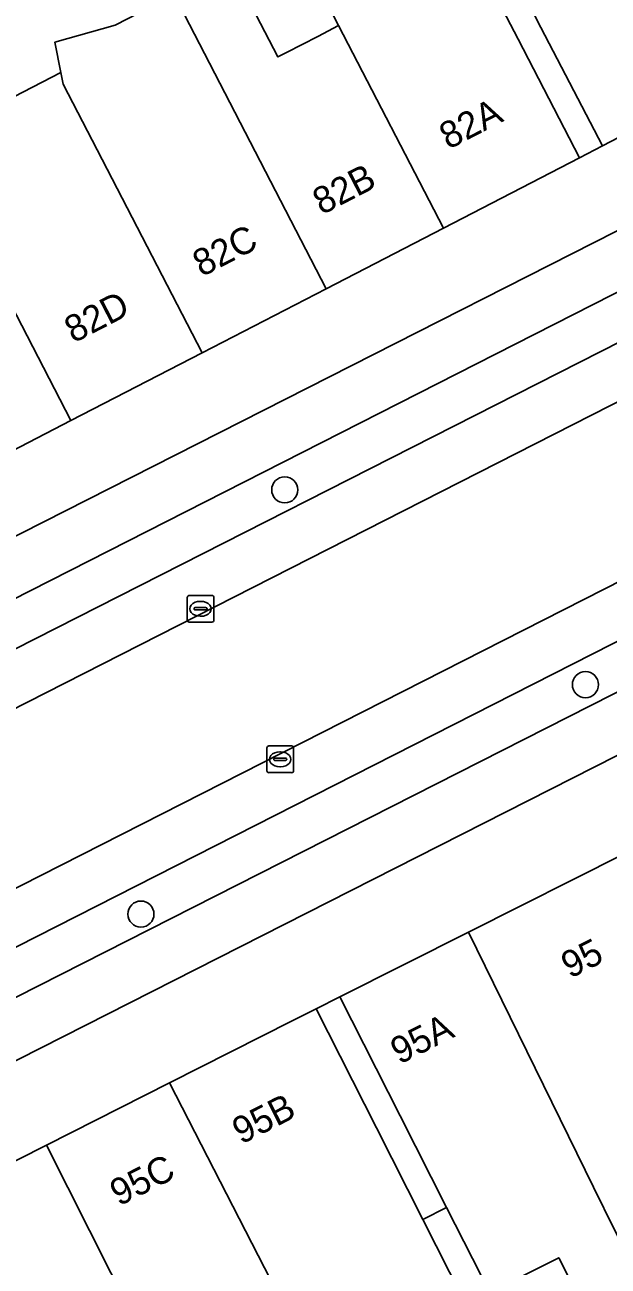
# Model space of a CAD drawing. Extents: x 158086 to 159499, y 382904 to 383981.
# Drawn here: x 158897.48 to 158919.33, y 383189.15 to 383235.68 of the extents above; entities that cross this region are included whole.
import ezdxf

# ---------------------------------------------------------------- set-up
doc = ezdxf.new("R2010")
doc.units = 0
for name, color, linetype in [('IMGEO_Berm_open', 7, 'Continuous'), ('IMGEO_Boom', 7, 'Continuous'), ('IMGEO_Erf', 7, 'Continuous'), ('IMGEO_Fietspad_gesloten', 7, 'Continuous'), ('IMGEO_Kolk', 7, 'Continuous'), ('IMGEO_Pand', 7, 'Continuous'), ('IMGEO_Pand_nummerreeks', 7, 'Continuous'), ('IMGEO_Pand_overbouw', 7, 'Continuous'), ('IMGEO_Parkeervlak_open', 7, 'Continuous'), ('IMGEO_Rijbaan_lokaal_gesloten', 7, 'Continuous'), ('IMGEO_Voetpad_open', 7, 'Continuous')]:
    doc.layers.add(name, color=color, linetype=linetype)

msp = doc.modelspace()

# ---------------------------------------------------------------- linework, layer by layer
at = {"layer": 'IMGEO_Berm_open'}
for points in [[(158877.802, 383202.135), (158878.263, 383202.712), (158937.072, 383232.587), (158946.787, 383237.376)], [(158941.643, 383236.699), (158932.546, 383232.204), (158896.237, 383213.737), (158887.748, 383209.162), (158884.368, 383207.233)], [(158934.379, 383218.139), (158933.615, 383219.659), (158877.108, 383190.925)], [(158874.019, 383187.49), (158934.379, 383218.139)]]:
    msp.add_lwpolyline(points, dxfattribs=at)
at = {"layer": 'IMGEO_Boom'}
for centre in [(158907.213, 383218.248), (158918.478, 383210.947), (158901.826, 383202.348)]:
    msp.add_circle(centre, 0.489, dxfattribs=at)
at = {"layer": 'IMGEO_Erf'}
for points in [[(158905.187, 383237.9), (158906.958, 383234.473), (158907.274, 383234.636), (158908.45, 383235.244), (158909.232, 383235.648), (158907.489, 383239.022)], [(158895.996, 383232.429), (158898.83, 383233.894), (158898.601, 383235.024), (158900.858, 383235.663), (158903.073, 383236.808)], [(158918.653, 383187.148), (158917.481, 383189.469), (158917.287, 383189.371), (158914.893, 383188.161), (158913.276, 383191.353), (158911.536, 383194.79), (158909.279, 383199.249), (158908.386, 383198.799), (158910.645, 383194.339), (158912.385, 383190.902), (158913.884, 383187.942)]]:
    msp.add_lwpolyline(points, dxfattribs=at)
at = {"layer": 'IMGEO_Fietspad_gesloten'}
for points in [[(158952.602, 383244.197), (158936.1, 383236.306), (158892.392, 383214.111), (158880.945, 383207.777), (158877.306, 383206.045)], [(158884.368, 383207.233), (158887.748, 383209.162), (158896.237, 383213.737), (158932.546, 383232.204), (158941.643, 383236.699)], [(158955.767, 383229.049), (158938.183, 383220.111), (158934.379, 383218.139), (158874.019, 383187.49), (158869.478, 383185.143), (158867.264, 383184.027), (158868.202, 383182.167), (158958.642, 383228.082)]]:
    msp.add_lwpolyline(points, dxfattribs=at)
at = {"layer": 'IMGEO_Kolk'}
for p, q in [((158903.56, 383213.364), (158903.56, 383214.216)), ((158903.635, 383214.29), (158904.487, 383214.29)), ((158904.048, 383214.07), (158904.073, 383214.07)), ((158904.561, 383214.216), (158904.561, 383213.364)), ((158903.819, 383213.784), (158903.819, 383213.796)), ((158904.257, 383213.747), (158903.859, 383213.747)), ((158903.862, 383213.833), (158904.26, 383213.833)), ((158904.303, 383213.796), (158904.303, 383213.784)), ((158904.487, 383213.29), (158903.635, 383213.29)), ((158904.071, 383213.51), (158904.046, 383213.51)), ((158906.545, 383207.723), (158906.545, 383208.575)), ((158906.62, 383208.649), (158907.472, 383208.649)), ((158907.033, 383208.429), (158907.058, 383208.429)), ((158907.546, 383208.575), (158907.546, 383207.723)), ((158906.804, 383208.143), (158906.804, 383208.155)), ((158907.242, 383208.106), (158906.844, 383208.106)), ((158906.847, 383208.192), (158907.245, 383208.192)), ((158907.288, 383208.155), (158907.288, 383208.143)), ((158907.472, 383207.649), (158906.62, 383207.649)), ((158907.056, 383207.869), (158907.031, 383207.869))]:
    msp.add_line(p, q, dxfattribs=at)
for points in [[(158903.56, 383213.364), (158903.56, 383214.216)], [(158903.635, 383214.29), (158904.487, 383214.29)], [(158904.561, 383214.216), (158904.561, 383213.364)], [(158904.487, 383213.29), (158903.635, 383213.29)], [(158906.545, 383207.723), (158906.545, 383208.575)], [(158906.62, 383208.649), (158907.472, 383208.649)], [(158907.546, 383208.575), (158907.546, 383207.723)], [(158907.472, 383207.649), (158906.62, 383207.649)]]:
    msp.add_lwpolyline(points, dxfattribs=at)
for centre, radius, start, end in [((158903.637, 383214.214), 0.0765, 91.552, 178.448), ((158903.637, 383214.214), 0.0765, 91.552, 178.448), ((158904.485, 383214.214), 0.0765, 1.552, 88.448), ((158904.485, 383214.214), 0.0765, 1.552, 88.448), ((158903.859, 383213.793), 0.0403, 85.8775, 175.7526), ((158903.856, 383213.783), 0.0366, 178.938, 274.7102), ((158904.26, 383213.79), 0.043, 264.8664, 352.4533), ((158904.264, 383213.795), 0.0386, 1.7309, 96.639), ((158903.637, 383213.366), 0.0765, 181.552, 268.448), ((158903.637, 383213.366), 0.0765, 181.552, 268.448), ((158904.485, 383213.366), 0.0765, 271.552, 358.448), ((158904.485, 383213.366), 0.0765, 271.552, 358.448), ((158906.622, 383208.573), 0.0765, 91.552, 178.448), ((158906.622, 383208.573), 0.0765, 91.552, 178.448), ((158907.47, 383208.573), 0.0765, 1.552, 88.448), ((158907.47, 383208.573), 0.0765, 1.552, 88.448), ((158906.844, 383208.152), 0.0403, 85.8775, 175.7526), ((158906.841, 383208.142), 0.0366, 178.938, 274.7102), ((158907.245, 383208.149), 0.043, 264.8664, 352.4533), ((158907.249, 383208.154), 0.0386, 1.7309, 96.639), ((158906.622, 383207.725), 0.0765, 181.552, 268.448), ((158906.622, 383207.725), 0.0765, 181.552, 268.448), ((158907.47, 383207.725), 0.0765, 271.552, 358.448), ((158907.47, 383207.725), 0.0765, 271.552, 358.448)]:
    msp.add_arc(centre, radius, start, end, dxfattribs=at)
for centre, major_axis, ratio, start_param, end_param in [((158904.047, 383213.79), (-0.387, 0.002), 0.722429, 4.712389, 7.853982), ((158904.072, 383213.79), (-0.39, 0.002), 0.717154, 1.570796, 4.712389), ((158907.032, 383208.149), (-0.387, 0.002), 0.722429, 4.712389, 7.853982), ((158907.057, 383208.149), (-0.39, 0.002), 0.717154, 1.570796, 4.712389)]:
    msp.add_ellipse(centre, major_axis=major_axis, ratio=ratio, start_param=start_param, end_param=end_param, dxfattribs=at)
at = {"layer": 'IMGEO_Pand'}
for points in [[(158918.51, 383245.411), (158915.333, 383244.713), (158916.684, 383242.097), (158917.505, 383240.514), (158914.974, 383239.199), (158916.813, 383235.583), (158919.116, 383231.144), (158924.425, 383233.898), (158923.549, 383235.588)], [(158915.964, 383235.134), (158914.35, 383238.239), (158911.655, 383236.87), (158909.86, 383240.343), (158907.489, 383239.022), (158909.232, 383235.648), (158913.156, 383228.054), (158918.259, 383230.691)], [(158909.232, 383235.648), (158908.45, 383235.244), (158907.274, 383234.636), (158906.958, 383234.473), (158905.187, 383237.9), (158903.073, 383236.808), (158908.768, 383225.787), (158913.156, 383228.054)], [(158903.073, 383236.808), (158900.858, 383235.663), (158898.601, 383235.024), (158898.83, 383233.894), (158898.919, 383233.453), (158900.192, 383230.993), (158904.122, 383223.386), (158908.768, 383225.787)], [(158900.192, 383230.993), (158898.919, 383233.453), (158898.83, 383233.894), (158895.996, 383232.429), (158895.677, 383233.046), (158893.486, 383231.914), (158899.205, 383220.845), (158904.122, 383223.386)], [(158893.486, 383231.914), (158890.868, 383230.561), (158888.104, 383229.133), (158889.842, 383225.744), (158891.508, 383222.496), (158893.803, 383218.054), (158899.205, 383220.845)], [(158922.21, 383200.164), (158919.952, 383204.624), (158914.098, 383201.676), (158918.782, 383192.11), (158919.561, 383190.519), (158920.112, 383189.428), (158925.743, 383192.27), (158924.003, 383195.718), (158924.368, 383195.902), (158924.072, 383196.486)], [(158914.098, 383201.676), (158909.279, 383199.249), (158911.536, 383194.79), (158913.276, 383191.353), (158914.893, 383188.161), (158917.287, 383189.371), (158917.481, 383189.469), (158918.653, 383187.148), (158920.733, 383188.198), (158920.112, 383189.428), (158919.561, 383190.519), (158918.782, 383192.11)], [(158910.645, 383194.339), (158908.386, 383198.799), (158907.494, 383198.348), (158902.902, 383196.023), (158906.935, 383188.166), (158907.105, 383188.252), (158908.744, 383185.007), (158911.48, 383186.389), (158911.344, 383186.659), (158913.884, 383187.942), (158912.385, 383190.902)], [(158898.286, 383193.686), (158903.913, 383182.537), (158906.361, 383183.773), (158908.744, 383185.007), (158907.105, 383188.252), (158906.935, 383188.166), (158902.902, 383196.023)], [(158898.286, 383193.686), (158893.049, 383191.034), (158897.173, 383183.144), (158898.209, 383181.162), (158898.316, 383180.957), (158900.333, 383181.976), (158900.774, 383182.199), (158900.986, 383182.306), (158901.487, 383181.312), (158903.913, 383182.537)]]:
    msp.add_lwpolyline(points, close=True, dxfattribs=at)
at = {"layer": 'IMGEO_Pand_overbouw'}
msp.add_lwpolyline([(158908.386, 383198.799), (158910.645, 383194.339), (158912.385, 383190.902), (158913.276, 383191.353), (158911.536, 383194.79), (158909.278, 383199.25)], close=True, dxfattribs=at)
at = {"layer": 'IMGEO_Parkeervlak_open'}
for points in [[(158946.787, 383237.376), (158937.072, 383232.587), (158878.263, 383202.712), (158877.802, 383202.135), (158877.293, 383200.595)], [(158876.412, 383199.523), (158939.858, 383231.815), (158950.446, 383237.021)], [(158953.486, 383231.854), (158932.711, 383221.414), (158878.508, 383193.847), (158873.446, 383191.309)], [(158877.108, 383190.925), (158933.615, 383219.659), (158937.429, 383221.586), (158951.341, 383228.53)]]:
    msp.add_lwpolyline(points, dxfattribs=at)
at = {"layer": 'IMGEO_Rijbaan_lokaal_gesloten'}
msp.add_lwpolyline([(158939.858, 383231.815), (158876.412, 383199.523), (158875.748, 383199.167), (158878.508, 383193.847), (158932.711, 383221.414), (158953.486, 383231.854), (158954.389, 383232.21), (158958.685, 383233.567), (158957.462, 383235), (158956.461, 383236.535), (158955.766, 383237.98), (158955.119, 383239.894), (158951.686, 383237.796), (158950.446, 383237.021)], close=True, dxfattribs=at)
at = {"layer": 'IMGEO_Voetpad_open'}
msp.add_lwpolyline([(158914.974, 383239.199), (158910.903, 383247.204), (158902.764, 383249.03), (158902.204, 383249.148), (158902.14, 383248.924), (158899.349, 383249.51), (158899.161, 383248.468), (158900.438, 383248.194), (158900.502, 383248.492), (158905.2, 383247.48), (158907.793, 383246.922), (158910.075, 383246.431), (158911.252, 383244.248), (158914.35, 383238.239), (158915.964, 383235.134), (158918.259, 383230.691), (158919.116, 383231.144), (158916.813, 383235.583)], close=True, dxfattribs=at)
for points in [[(158951.581, 383247.918), (158924.425, 383233.898), (158919.116, 383231.144), (158918.259, 383230.691), (158913.156, 383228.054), (158908.768, 383225.787), (158904.122, 383223.386), (158899.205, 383220.845), (158893.803, 383218.054), (158892.879, 383217.576), (158887.55, 383214.822), (158882.249, 383212.084), (158882.178, 383212.219), (158879.476, 383210.871), (158865.702, 383204.223)], [(158877.306, 383206.045), (158880.945, 383207.777), (158892.392, 383214.111), (158936.1, 383236.306), (158952.602, 383244.197)], [(158958.642, 383228.082), (158868.202, 383182.167), (158869.739, 383179.189), (158871.746, 383180.263), (158871.926, 383180.367), (158872.178, 383180.494), (158881.915, 383185.397), (158882.53, 383185.708), (158887.717, 383188.335), (158893.049, 383191.034), (158898.286, 383193.686), (158902.902, 383196.023), (158907.494, 383198.348), (158908.386, 383198.799), (158909.279, 383199.249), (158914.098, 383201.676), (158919.952, 383204.624)]]:
    msp.add_lwpolyline(points, dxfattribs=at)

# ---------------------------------------------------------------- texts
at = {"layer": 'IMGEO_Pand_nummerreeks'}
for s, rotation, p in [('82A', 27.3244, (158913.345, 383230.989)), ('82B', 27.3244, (158908.599, 383228.537)), ('82C', 27.3244, (158904.104, 383226.214)), ('82D', 27.3244, (158899.301, 383223.732)), ('95', 26.7285, (158917.898, 383199.917)), ('95A', 26.7342, (158911.507, 383196.698)), ('95B', 26.8488, (158905.58, 383193.703)), ('95C', 26.8593, (158900.999, 383191.384))]:
    msp.add_text(s, height=1, rotation=rotation, dxfattribs=at).set_placement(p)

doc.saveas('drawing.dxf')
